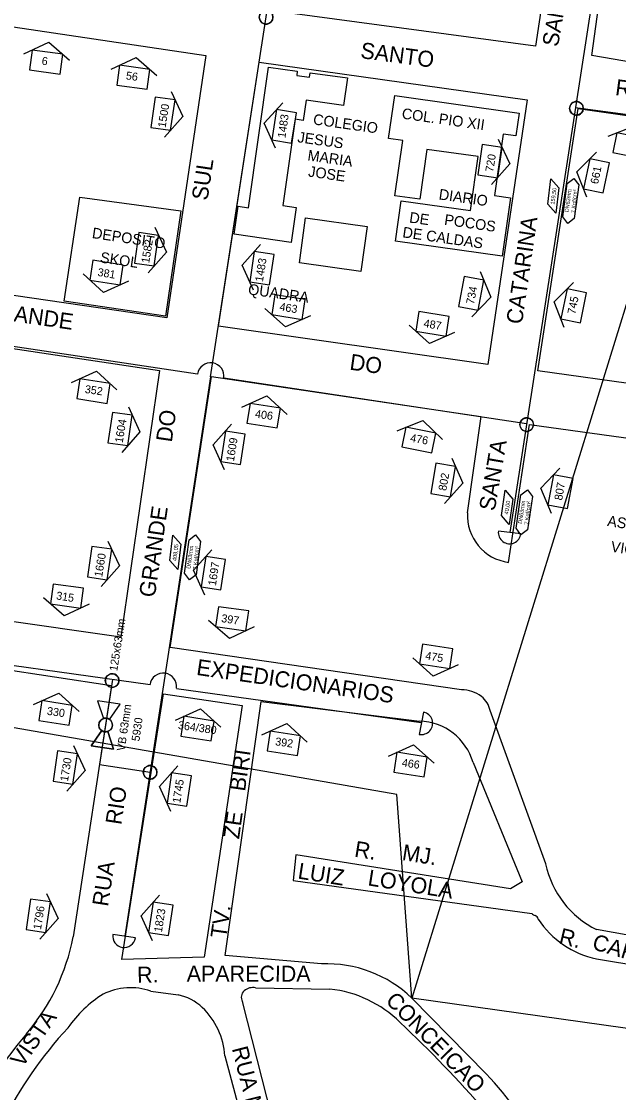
# Model space of a CAD drawing. Extents: x 325709 to 364434, y 7573432 to 7597073.
# Drawn here: x 338188.7 to 338412.3, y 7589064.5 to 7589465.9 of the extents above; entities that cross this region are included whole.
import ezdxf

# ---------------------------------------------------------------- set-up
doc = ezdxf.new("R2010")
doc.units = 0
for name, color, linetype in [('EDIFEXISTENT', 7, 'Continuous'), ('EDIFIDENTIF', 7, 'Continuous'), ('FORMATO', 7, 'Continuous'), ('LIMITE_BAIRROS_MUNICIPIOS', 7, 'Continuous'), ('LOGRADOURO', 7, 'Continuous'), ('LOGRADOURO_TEXTO', 7, 'Continuous'), ('NUM_REF', 7, 'Continuous'), ('SIMBOLO', 7, 'Continuous'), ('TEXTO', 7, 'Continuous'), ('TUBO_PEAD_GN_125', 7, 'Continuous'), ('TUBO_PEAD_GN_63', 7, 'Continuous'), ('VALVULA_PEAD_63', 7, 'Continuous'), ('VES - BLOQUEIIO', 7, 'Continuous')]:
    doc.layers.add(name, color=color, linetype=linetype)

# ---------------------------------------------------------------- blocks, each defined once
blk = doc.blocks.new('INTERLIGACAO')
at = {"layer": 'SIMBOLO'}
blk.add_circle((0, 0), 1.28, dxfattribs=at)
for start, end in [(0, 180), (180, 0)]:
    blk.add_arc((0, 0), 1.28, start, end, dxfattribs=at)
blk = doc.blocks.new('VALVULA_PEAD_DN_63')
at = {"layer": 'VALVULA_PEAD_63'}
for points in [[(-1.14, 0.57), (-4.25, 2.13), (-4.25, -2.13), (-1.14, -0.57)], [(-1.14, -0.57), (-4.25, -2.13), (-4.25, 2.13), (-1.14, 0.57)], [(1.14, -0.57), (4.25, -2.13), (4.25, 2.13), (1.14, 0.57)], [(1.14, -0.57), (4.25, -2.13), (4.25, 2.13), (1.14, 0.57)]]:
    blk.add_lwpolyline(points, dxfattribs=at)
blk.add_circle((0, 0), 1.28, dxfattribs=at)
for start, end in [(90, 270), (153.4349, 206.5651), (270, 90), (0, 26.5651), (333.4349, 0)]:
    blk.add_arc((0, 0), 1.28, start, end, dxfattribs=at)
blk = doc.blocks.new('NUM_REF')
at = {"layer": 'NUM_REF'}
blk.add_lwpolyline([(-4.3125, 0.9375), (0, 3.75), (4.3125, 0.9375)], dxfattribs=at)
blk.add_lwpolyline([(2.875, -1.875), (2.875, 1.875), (-2.875, 1.875), (-2.875, -1.875)], close=True, dxfattribs=at)

msp = doc.modelspace()

# ---------------------------------------------------------------- linework, layer by layer
at = {"layer": 'EDIFEXISTENT'}
for p, q in [((338273.74, 7589396.03), (338281.22, 7589448.72)), ((338281.22, 7589448.72), (338292.01, 7589447.19)), ((338292.01, 7589447.19), (338291.78, 7589445.63)), ((338296.57, 7589444.95), (338296.81, 7589446.6)), ((338296.81, 7589446.6), (338310.8, 7589444.7)), ((338291.78, 7589445.63), (338296.57, 7589444.95)), ((338310.8, 7589444.7), (338309.33, 7589434.37)), ((338295.32, 7589436.35), (338294.24, 7589428.78)), ((338309.33, 7589434.37), (338295.32, 7589436.35)), ((338326.11, 7589421.93), (338328.49, 7589438.13)), ((338328.49, 7589438.13), (338375.08, 7589431.52)), ((338375.08, 7589431.52), (338373.87, 7589422.99)), ((338291.22, 7589429.21), (338286.62, 7589396.85)), ((338294.24, 7589428.78), (338291.22, 7589429.21)), ((338369.12, 7589423.66), (338365.85, 7589400.66)), ((338373.87, 7589422.99), (338369.12, 7589423.66)), ((338331.47, 7589421.17), (338326.11, 7589421.93)), ((338328.54, 7589400.55), (338331.47, 7589421.17)), ((338340.49, 7589417.9), (338337.84, 7589399.23)), ((338359.69, 7589415.18), (338340.49, 7589417.9)), ((338356.82, 7589394.95), (338359.69, 7589415.18)), ((338204.77, 7589361.02), (338210.56, 7589400.04)), ((338210.56, 7589400.04), (338248.45, 7589394.82)), ((338337.84, 7589399.23), (338328.54, 7589400.55)), ((338328.77, 7589383.51), (338330.92, 7589398.63)), ((338330.92, 7589398.63), (338356.82, 7589394.95)), ((338365.85, 7589400.66), (338371.84, 7589399.81)), ((338371.84, 7589399.81), (338368.72, 7589377.84)), ((338248.45, 7589394.82), (338242.6, 7589355.41)), ((338268.41, 7589386.08), (338269.9, 7589396.57)), ((338269.9, 7589396.57), (338273.74, 7589396.03)), ((338286.62, 7589396.85), (338291.55, 7589396.15)), ((338291.55, 7589396.15), (338289.69, 7589383.06)), ((338292.89, 7589375.38), (338295.14, 7589392.25)), ((338295.14, 7589392.25), (338318.21, 7589388.97)), ((338318.21, 7589388.97), (338315.82, 7589372.13)), ((338289.69, 7589383.06), (338268.41, 7589386.08)), ((338368.72, 7589377.84), (338328.77, 7589383.51)), ((338315.82, 7589372.13), (338292.89, 7589375.38)), ((338242.6, 7589355.41), (338204.77, 7589361.02))]:
    msp.add_line(p, q, dxfattribs=at)
at = {"layer": 'LIMITE_BAIRROS_MUNICIPIOS'}
for points in [[(338657.19, 7589909.08), (338624.06, 7589719.21), (338521.53, 7589704.01), (338334.9, 7589099.85)], [(338693.32, 7588899.85), (338676.46, 7589072.92), (338566.53, 7589067.28), (338334.9, 7589099.85), (338329.24, 7589176.21), (337839.73, 7589261.51)]]:
    msp.add_lwpolyline(points, dxfattribs=at)
at = {"layer": 'LOGRADOURO'}
for p, q in [((338388.11, 7589501.91), (338381.23, 7589456.64)), ((338402.33, 7589453.06), (338409.03, 7589501.91)), ((338157.07, 7589467.98), (338257.79, 7589453.14)), ((338381.23, 7589456.64), (338280.89, 7589470.02)), ((338257.79, 7589453.14), (338243.2, 7589354.77)), ((338262.55, 7589351.64), (338277.7, 7589450.56)), ((338277.7, 7589450.56), (338378.02, 7589436.48)), ((338378.02, 7589436.48), (338363.35, 7589337.33)), ((338382.04, 7589334.98), (338397.17, 7589433.19)), ((338243.2, 7589354.77), (338142.4, 7589369.44)), ((338363.35, 7589337.33), (338262.55, 7589351.64)), ((338139.72, 7589350.13), (338240.42, 7589334.99)), ((338240.42, 7589334.99), (338225.93, 7589235.07)), ((338481.39, 7589320.82), (338382.04, 7589334.98)), ((338244.42, 7589231.23), (338259.87, 7589332.82)), ((338259.87, 7589332.82), (338360.68, 7589317.75)), ((338360.68, 7589317.75), (338355.67, 7589281.7)), ((338371.13, 7589263.15), (338378.99, 7589314.84)), ((338378.99, 7589314.84), (338479.89, 7589300.71)), ((338225.93, 7589235.07), (338125.28, 7589249.61)), ((338122.86, 7589232.14), (338222.49, 7589217.04)), ((338353.47, 7589215.36), (338244.42, 7589231.23)), ((338222.49, 7589217.04), (338208.09, 7589122.86)), ((338226.37, 7589114.35), (338241.85, 7589213.88)), ((338241.85, 7589213.88), (338271.35, 7589209.47)), ((338265.03, 7589115.84), (338278.47, 7589211.01)), ((338278.47, 7589211.01), (338337.82, 7589203.64)), ((338271.35, 7589209.47), (338257.2, 7589115.22)), ((338385.01, 7589150.15), (338364.21, 7589207.65)), ((338357.81, 7589188.16), (338357.81, 7589188.16)), ((338357.81, 7589188.16), (338376.2, 7589143.47)), ((338452.63, 7589117.01), (338404.05, 7589125.54)), ((338257.2, 7589115.22), (338226.37, 7589114.35)), ((338301.12, 7589112.69), (338265.03, 7589115.84)), ((338404.05, 7589114.64), (338448.77, 7589107.12)), ((338237.22, 7589102.5), (338247.39, 7589101.1)), ((338276.42, 7589103.72), (338304.18, 7589103.24)), ((338296.19, 7589001.91), (338271.46, 7589098.56)), ((338362.77, 7589071.45), (338334.9, 7589099.85)), ((338264.9, 7589078.21), (338285.18, 7589001.91))]:
    msp.add_line(p, q, dxfattribs=at)
for points in [[(338481.39, 7589423.97), (338449.46, 7589444.91), (338402.33, 7589453.06)], [(338397.17, 7589433.19), (338447.14, 7589426.11), (338481.39, 7589402.52)], [(338291.46, 7589153.6), (338290.51, 7589143.94), (338379.85, 7589131.61)], [(338376.2, 7589143.47), (338371.79, 7589140.85), (338291.46, 7589153.6)]]:
    msp.add_lwpolyline(points, dxfattribs=at)
for centre, radius, start, end in [((338373.5, 7589280.83), 17.84, 177.2035, 262.366), ((338353.66, 7589203.48), 11.89, 52.176, 90.9414), ((338355.54, 7589205.87), 8.85, 11.6262, 52.3043), ((338337.3, 7589182.33), 21.32, 15.8838, 88.5965), ((338420.01, 7589157.56), 35.78, 191.9519, 243.5023), ((338381.76, 7589133.18), 2.48, 219.5267, 254.3995), ((338380.27, 7589128.96), 2.02, 15.8325, 65.9594), ((338410.77, 7589147.99), 34.02, 212.9039, 258.5939), ((338131.29, 7589137.45), 78.17, 319.3335, 349.2385), ((338303.11, 7589067.07), 45.66, 45.8734, 92.4912), ((338229.64, 7589080.59), 23.19, 70.9232, 116.5706), ((338274.18, 7589100.18), 3.17, 129.6604, 210.7074), ((338275.39, 7589098.89), 4.94, 78.0117, 130.9221), ((338299.51, 7589059.37), 44.12, 45.3625, 83.9139), ((338243.88, 7589062.54), 45.94, 122.4043, 145.2146), ((338243.46, 7589082.44), 19.07, 47.0678, 78.1126), ((338236.99, 7589076.3), 27.98, 3.9189, 45.9325), ((338037.09, 7588777.03), 429.55, 40.7633, 46.9168), ((338299.57, 7588994.15), 142.85, 139.717, 176.8841), ((338319.86, 7588983.47), 154.95, 137.2041, 169.2324), ((338240.92, 7588957.8), 166.62, 30.5054, 43.0062)]:
    msp.add_arc(centre, radius, start, end, dxfattribs=at)
at = {"layer": 'SIMBOLO'}
for points in [[(338389.98, 7589403.55), (338388.84, 7589394.01), (338385.85, 7589397.39), (338386.99, 7589406.93)], [(338391.4, 7589392.62), (338393.07, 7589405.13), (338395.53, 7589407.01), (338395.53, 7589407.01), (338397.41, 7589404.56), (338395.74, 7589392.04), (338393.28, 7589390.16), (338393.28, 7589390.16)], [(338372.71, 7589286.81), (338371.31, 7589277.3), (338368.41, 7589280.76), (338369.81, 7589290.27)], [(338373.91, 7589275.95), (338375.74, 7589288.44), (338378.22, 7589290.29), (338378.22, 7589290.29), (338380.07, 7589287.81), (338378.23, 7589275.31), (338375.75, 7589273.47), (338375.75, 7589273.47)], [(338248.39, 7589269.99), (338247.25, 7589260.45), (338244.25, 7589263.83), (338245.4, 7589273.37)], [(338249.81, 7589259.06), (338251.48, 7589271.58), (338253.94, 7589273.46), (338253.94, 7589273.46), (338255.82, 7589271), (338254.15, 7589258.48), (338251.69, 7589256.6), (338251.69, 7589256.6)]]:
    msp.add_lwpolyline(points, close=True, dxfattribs=at)
at = {"layer": 'TUBO_PEAD_GN_125'}
for p, q in [((338108.98, 7589235.3), (338236.86, 7589217.34)), ((338246.76, 7589215.95), (338338.33, 7589203.1)), ((338339.28, 7589207.05), (338337.58, 7589198.71))]:
    msp.add_line(p, q, dxfattribs=at)
for centre, radius, start, end in [((338241.81, 7589216.65), 5, 352.0073, 172.0073), ((338338.43, 7589202.88), 4.25, 258.4824, 78.4824)]:
    msp.add_arc(centre, radius, start, end, dxfattribs=at)
at = {"layer": 'TUBO_PEAD_GN_63'}
for p, q in [((338259.51, 7589332.64), (338296.9, 7589574.35)), ((338415.24, 7589557.72), (338371.61, 7589274.36)), ((338396.2, 7589433.6), (338446.51, 7589426.78)), ((338254.61, 7589333.66), (337902.13, 7589386.86)), ((338259.51, 7589332.64), (338242.15, 7589218.86)), ((338377.84, 7589315.07), (338264.5, 7589332.17)), ((338375.75, 7589273.89), (338367.3, 7589274.85)), ((338242.15, 7589218.86), (338227.48, 7589123.04)), ((338231.38, 7589122.45), (338222.97, 7589123.73))]:
    msp.add_line(p, q, dxfattribs=at)
msp.add_lwpolyline([(338222.84, 7589219.31), (338217.95, 7589187.38), (338236.89, 7589184.49)], dxfattribs=at)
for centre, radius, start, end in [((338259.56, 7589332.92), 5, 351.4178, 171.4178), ((338371.52, 7589274.37), 4.25, 173.5133, 353.5133), ((338227.17, 7589123.09), 4.25, 171.2971, 351.2971)]:
    msp.add_arc(centre, radius, start, end, dxfattribs=at)

# ---------------------------------------------------------------- block references
at = {"layer": 'FORMATO'}
for p, xscale, yscale, rotation in [((338197.97, 7589450.63), 1.9999999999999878, 1.9999999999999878, -7.737506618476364), ((338230.65, 7589444.95), 1.9999999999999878, 1.9999999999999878, -7.737506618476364), ((338241.71, 7589431.28), 1.9999999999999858, 1.9999999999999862, -98.26508109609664), ((338287.05, 7589426.56), 1.9999999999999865, 1.9999999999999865, 80.95103804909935), ((338416.54, 7589419.31), 1.9999999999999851, 1.9999999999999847, -11.292539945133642), ((338364.17, 7589413.51), 1.9999999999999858, 1.9999999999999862, -98.26508109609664), ((338404.07, 7589408.01), 1.9999999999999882, 1.9999999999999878, 78.14993266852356), ((338235.56, 7589380.48), 1.9999999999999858, 1.9999999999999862, -98.26508109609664), ((338278.75, 7589373.4), 1.9999999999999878, 1.9999999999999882, 81.33720200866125), ((338220.59, 7589371.74), 1.9999999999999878, 1.999999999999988, 170.9627695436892), ((338357.1, 7589363.96), 1.9999999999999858, 1.9999999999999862, -100.56731469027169), ((338395.5, 7589359.25), 1.9999999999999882, 1.9999999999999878, 78.14993266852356), ((338288.71, 7589358.8), 1.9999999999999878, 1.999999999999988, 170.9627695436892), ((338342.66, 7589352.54), 1.9999999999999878, 1.999999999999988, 170.9627695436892), ((338215.68, 7589327.33), 1.9999999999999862, 1.9999999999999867, -8.929111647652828), ((338279.41, 7589318.1), 1.9999999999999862, 1.9999999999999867, -8.929111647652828), ((338225.65, 7589313.14), 1.9999999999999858, 1.9999999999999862, -98.26508109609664), ((338267.91, 7589306.09), 1.9999999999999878, 1.9999999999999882, 81.33720200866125), ((338337.52, 7589308.97), 1.9999999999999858, 1.9999999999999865, -11.04778855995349), ((338346.65, 7589294.05), 1.9999999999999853, 1.9999999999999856, -99.28195134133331), ((338390.58, 7589289.62), 1.9999999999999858, 1.9999999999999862, 79.37237527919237), ((338217.97, 7589262.89), 1.9999999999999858, 1.9999999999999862, -98.26508109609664), ((338260.56, 7589259.1), 1.9999999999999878, 1.9999999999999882, 81.33720200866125), ((338205.8, 7589250.51), 1.9999999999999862, 1.999999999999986, 172.03355075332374), ((338267.62, 7589242.02), 1.9999999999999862, 1.999999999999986, 172.03355075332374), ((338344.03, 7589227.97), 1.9999999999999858, 1.9999999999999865, 171.2317346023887), ((338201.5, 7589206.74), 1.9999999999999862, 1.9999999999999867, -8.929111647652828), ((338254.62, 7589200.88), 1.9999999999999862, 1.9999999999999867, -8.929111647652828), ((338286.95, 7589195.32), 1.9999999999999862, 1.9999999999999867, -8.929111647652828), ((338205.14, 7589186.28), 1.9999999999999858, 1.9999999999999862, -98.26508109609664), ((338334.39, 7589187.38), 1.9999999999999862, 1.9999999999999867, -8.929111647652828), ((338247.81, 7589178.07), 1.9999999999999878, 1.9999999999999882, 81.33720200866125), ((338195.03, 7589130.75), 1.9999999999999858, 1.9999999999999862, -98.26508109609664), ((338240.92, 7589129.63), 1.9999999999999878, 1.9999999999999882, 81.33720200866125)]:
    msp.add_blockref('NUM_REF', p, dxfattribs=dict(at, xscale=xscale, yscale=yscale, rotation=rotation))
at = {"layer": 'SIMBOLO'}
for p, xscale, yscale, rotation in [((338280.35, 7589467.4), 2.0000000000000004, 1.9999999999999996, 22.031790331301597), ((338396.54, 7589433.28), 2.0000000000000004, 1.9999999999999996, 22.031790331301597), ((338377.9, 7589314.76), 2.0000000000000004, 1.9999999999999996, 22.031790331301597), ((338222.69, 7589218.87), 2, 2.0000000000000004, 80.92216635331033), ((338236.89, 7589184.49), 2, 2.0000000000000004, 80.92216635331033)]:
    msp.add_blockref('INTERLIGACAO', p, dxfattribs=dict(at, xscale=xscale, yscale=yscale, rotation=rotation))
at = {"layer": 'VES - BLOQUEIIO', "xscale": 1.9999999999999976, "yscale": 1.9999999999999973, "rotation": 81.81330784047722}
msp.add_blockref('VALVULA_PEAD_DN_63', (338220.22, 7589202.21), dxfattribs=at)

# ---------------------------------------------------------------- texts
for s, rotation, p in [('6', 351.9807, (338196.16, 7589449.69)), ('56', 351.9807, (338227.69, 7589444.16)), ('1500', 80.7773, (338242.69, 7589425.89)), ('1483', 81.8795, (338287.56, 7589422.03)), ('720', 80.7773, (338365.33, 7589409.28)), ('661', 78.7011, (338404.63, 7589404.71)), ('1582', 80.7773, (338236.54, 7589375.1)), ('1483', 81.0554, (338279.12, 7589368.12)), ('381', 350.5497, (338217.07, 7589370.53)), ('734', 78.4751, (338358.1, 7589359.68)), ('745', 78.7011, (338396.05, 7589355.95)), ('463', 350.5497, (338285.19, 7589357.59)), ('487', 350.5497, (338339.15, 7589351.34)), ('352', 351.9994, (338212.31, 7589326.65)), ('406', 351.9994, (338276.04, 7589317.42)), ('1604', 80.7773, (338226.63, 7589307.76)), ('476', 349.8807, (338334.13, 7589308.42)), ('1609', 81.0554, (338268.29, 7589300.81)), ('802', 79.7604, (338347.75, 7589289.79)), ('807', 80.3009, (338391.16, 7589286.23)), ('1660', 80.7773, (338218.95, 7589257.5)), ('1697', 81.3372, (338261.52, 7589254.24)), ('315', 351.0759, (338201.57, 7589249.32)), ('125x63mm', 80.9222, (338224.58, 7589222.23)), ('397', 351.0759, (338263.39, 7589240.83)), ('475', 350.2741, (338339.79, 7589226.84)), ('VB 63mm', 81.8133, (338227.37, 7589192.33)), ('330', 351.9994, (338198.13, 7589206.06)), ('5930', 81.8133, (338232.87, 7589195.95)), ('364/380', 351.9994, (338247.21, 7589200.77)), ('392', 351.9994, (338283.58, 7589194.64)), ('1730', 80.7773, (338206.12, 7589180.89)), ('466', 351.9994, (338331.02, 7589186.7)), ('1745', 81.0554, (338248.19, 7589172.79)), ('1796', 80.7773, (338196.02, 7589125.37)), ('1823', 81.0554, (338241.3, 7589124.36))]:
    msp.add_text(s, height=3, rotation=rotation).set_placement(p)
at = {"layer": 'EDIFIDENTIF'}
for s, rotation, p in [('COLEGIO', 351.9195, (338297.75, 7589427.29)), ('COL. PIO XII', 351.9195, (338330.96, 7589429.47)), ('JESUS', 351.9195, (338291.9, 7589420.62)), ('MARIA', 351.9195, (338295.67, 7589413.79)), ('JOSE', 351.9195, (338295.92, 7589407.76)), ('DIARIO', 351.9195, (338344.8, 7589399.19)), ('DE', 351.9195, (338333.77, 7589390.52)), ('POCOS', 351.9195, (338346.87, 7589389.69)), ('DEPOSITO', 351.5606, (338214.96, 7589384.71)), ('DE CALDAS', 351.9195, (338331.22, 7589384.98)), ('SKOL', 351.5606, (338217.99, 7589375.55)), ('QUADRA', 351.9195, (338273.41, 7589363.62)), ('ASILO SAO', 351.5585, (338407.89, 7589276.8)), ('VICENTE  DE', 351.5585, (338409.21, 7589267.19))]:
    msp.add_text(s, height=4, rotation=rotation, dxfattribs=at).set_placement(p)
at = {"layer": 'LOGRADOURO_TEXTO'}
for s, rotation, p in [('SANTA', 80.2658, (338389.61, 7589456.12)), ('SANTO', 352.4083, (338315.42, 7589452.14)), ('RUA XV', 352.4083, (338410.82, 7589438.3)), ('SUL', 81.5606, (338258.38, 7589398.55)), ('CATARINA', 81.7587, (338376.14, 7589352.15)), ('GRANDE', 351.7218, (338173.7, 7589355.2)), ('DO', 351.9195, (338311.36, 7589335.4)), ('DO', 81.748, (338245, 7589307.95)), ('SANTA', 80.2658, (338365.93, 7589282.19)), ('GRANDE', 81.748, (338238.64, 7589249.79)), ('EXPEDICIONARIOS', 351.78, (338253.99, 7589221.02)), ('BIRI', 81.965, (338272.43, 7589177.13)), ('RIO', 81.3071, (338226.08, 7589164.59)), ('ZE', 81.965, (338270.19, 7589159.27)), ('R.', 350.9796, (338313.13, 7589152.89)), ('MJ.', 350.9796, (338330.98, 7589151.65)), ('RUA', 81.3071, (338221.12, 7589133.97)), ('LUIZ', 350.9796, (338291.94, 7589144.72)), ('LOYOLA', 350.9796, (338318.15, 7589142.15)), ('TV.', 81.965, (338265.41, 7589122.09)), ('R.', 346.3584, (338389.67, 7589120.41)), ('CAP.', 343.5372, (338402.06, 7589118.32)), ('R.', 1.539, (338232.08, 7589105.58)), ('APARECIDA', 359.9302, (338250.61, 7589106.07)), ('CONCEICAO', 314.4035, (338324.72, 7589098.6)), ('VISTA', 55.477, (338189.1, 7589073.61)), ('RUA MATILDE COSTA', 284.3533, (338267.48, 7589081))]:
    msp.add_text(s, height=6, rotation=rotation, dxfattribs=at).set_placement(p)
at = {"layer": 'TEXTO'}
for s, rotation, p in [('159,50', 83.1646, (338388.33, 7589397.16)), ('DN63mm', 82.4089, (338393.57, 7589394.23)), ('7 Kgf/cm²', 84.9637, (338396.04, 7589393.93)), ('40,00', 81.5755, (338370.97, 7589281.04)), ('DN63mm', 81.6558, (338376.1, 7589277.54)), ('7 Kgf/cm²', 84.2106, (338378.56, 7589277.2)), ('408,05', 83.1646, (338246.74, 7589263.6)), ('DN63mm', 82.4089, (338251.98, 7589260.68)), ('7 Kgf/cm²', 84.9637, (338254.45, 7589260.37))]:
    msp.add_text(s, height=1.5, rotation=rotation, dxfattribs=at).set_placement(p)

doc.saveas('drawing.dxf')
